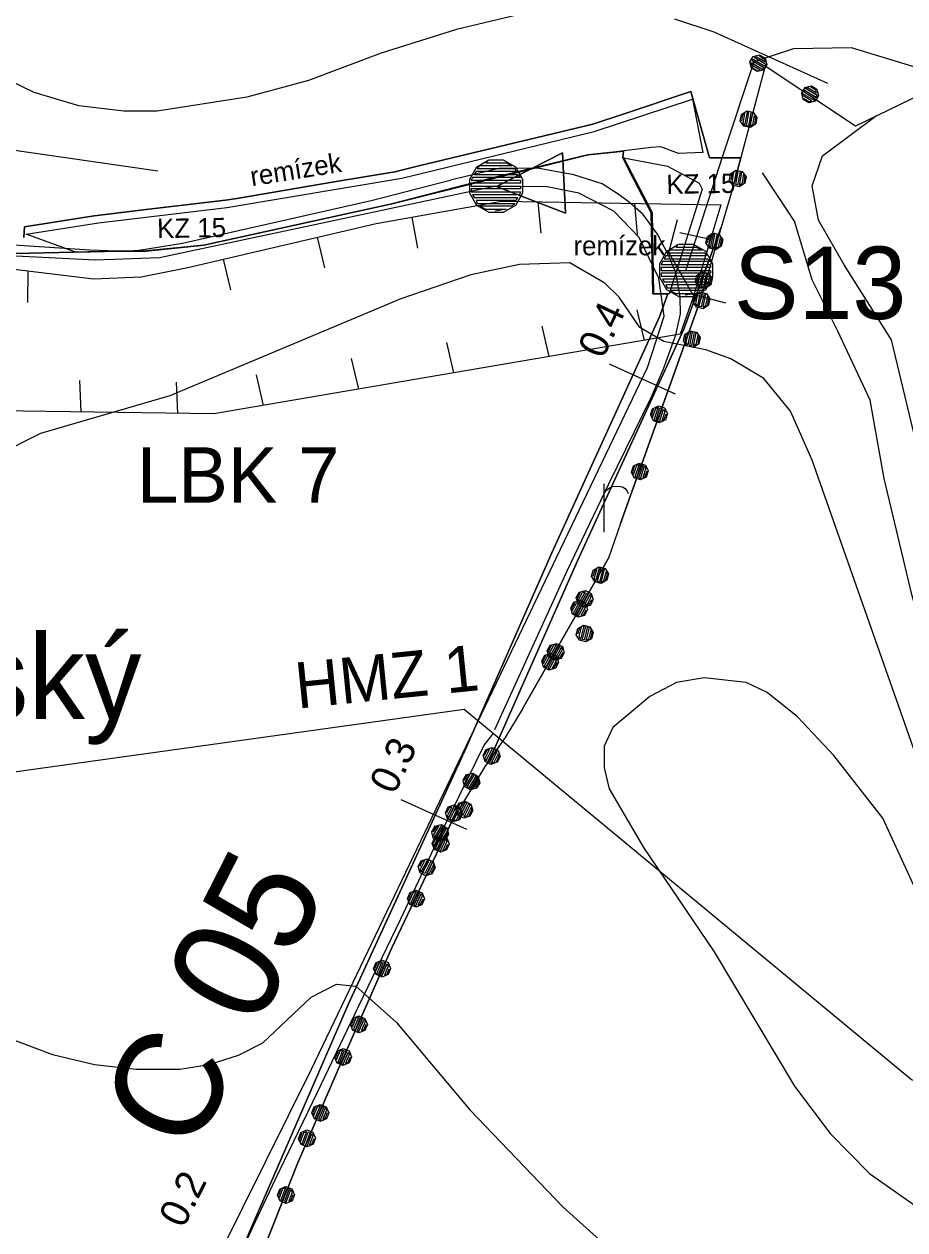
# Model space of a CAD drawing. Extents: x -645676 to -642474, y -1077513 to -1072613.
# Drawn here: x -643934.1 to -643751.8, y -1077150 to -1076900.3 of the extents above; entities that cross this region are included whole.
import ezdxf

# ---------------------------------------------------------------- set-up
doc = ezdxf.new("R2010")
doc.units = 0
for name, color, linetype in [('katastr_ln___zem____popis', 7, 'Continuous'), ('KRAJ_ZELEN_STAV', 7, 'Continuous'), ('Krajinn__zele____popis___stav', 7, 'Continuous'), ('KULTURY_STAV', 7, 'Continuous'), ('KULTURY_ZNACKY', 7, 'Continuous'), ('Lok_ln__biokoridor___navr_en_', 7, 'Continuous'), ('OBVOD_PU', 7, 'Continuous'), ('Odvodnen__cesty_pod_lnou_dren_____navr_en_', 7, 'Continuous'), ('Odvodnen__cesty_pr_kopem___navr_en_', 7, 'Continuous'), ('PC_NAVRH', 7, 'Continuous'), ('PC_OBJ_POPIS_NAVRH', 7, 'Continuous'), ('PC_OBJEKTY_NAVRH', 7, 'Continuous'), ('PC_POPIS_NAVRH', 7, 'Continuous'), ('PC_STAN_NAVRH', 7, 'Continuous'), ('SPRAV_HR_STAV', 7, 'Continuous'), ('USES_BK_NAVRH', 7, 'Continuous'), ('VHO_V_MZ_STAV', 7, 'Continuous'), ('VRSTEVNICE', 7, 'Continuous')]:
    doc.layers.add(name, color=color, linetype=linetype)

# ---------------------------------------------------------------- blocks, each defined once
blk = doc.blocks.new('$406')
blk.add_lwpolyline([(-0.19, 0.72), (0.2, 0.72), (0.54, 0.53), (0.73, 0.19), (0.73, -0.2), (0.54, -0.54), (0.2, -0.73), (-0.19, -0.73), (-0.53, -0.54), (-0.72, -0.2), (-0.72, 0.19), (-0.53, 0.53), (-0.2, 0.72), (-0.28, 0.64), (0.28, 0.64), (0.44, 0.56), (-0.44, 0.56), (-0.52, 0.48), (0.52, 0.48), (0.56, 0.4), (-0.55, 0.4), (-0.6, 0.32), (0.6, 0.32), (0.68, 0.24), (-0.59, 0.24), (-0.65, 0.24), (-0.68, 0.16), (0.59, 0.16), (0.68, 0.16), (0.68, 0.08), (-0.59, 0.08), (-0.68, 0.08), (-0.68, 0), (0.59, 0), (0.68, 0), (0.68, -0.08), (-0.59, -0.08), (-0.68, -0.08), (-0.68, -0.16), (0.59, -0.16), (0.68, -0.16), (0.65, -0.24), (-0.62, -0.24), (-0.65, -0.24), (-0.6, -0.32), (0.6, -0.32), (0.56, -0.4), (-0.55, -0.4), (-0.52, -0.48), (0.52, -0.48), (0.44, -0.56), (-0.44, -0.56), (-0.28, -0.64), (0.28, -0.64), (-0.02, -0.69)])
blk = doc.blocks.new('$944')
blk.add_line((0, 1.5), (0, -1.5))
blk = doc.blocks.new('$920')
for points in [[(0, 0), (-2.8, 1.25), (-2.8, -1.25), (0, 0)], [(-2.8, 1.25), (0, 0), (-2.8, -1.25), (-2.8, 1.25)]]:
    blk.add_lwpolyline(points)
blk = doc.blocks.new('$479')
for points in [[(0, 0), (0, 1.27), (0, 2)], [(0, 1.6), (0.1, 1.73), (0.23, 1.84), (0.37, 1.89), (0.6, 1.9), (0.77, 1.87), (0.87, 1.8), (0.96, 1.7), (1, 1.6)]]:
    blk.add_lwpolyline(points)
blk = doc.blocks.new('$935')
blk.add_lwpolyline([(-2, -1), (-1, 0), (1, 0), (2, -1)])
blk = doc.blocks.new('2$1030')
blk.add_line((0, 0), (0, -0.5))
blk = doc.blocks.new('2$0620')
for points in [[(-1.07, 0.32), (-0.88, 0.13), (-0.88, -0.14), (-1.07, -0.33), (-1.34, -0.33), (-1.53, -0.14), (-1.53, 0.13), (-1.34, 0.32), (-1.07, 0.32), (-1.08, 0.28), (-1.32, 0.28), (-1.4, 0.2), (-1, 0.2), (-0.92, 0.12), (-1.48, 0.12), (-1.48, 0.04), (-0.92, 0.04), (-0.92, -0.04), (-1.48, -0.04), (-1.48, -0.12), (-0.92, -0.12), (-1, -0.2), (-1.4, -0.2), (-1.32, -0.28), (-1.08, -0.28)], [(1.43, 0.32), (1.62, 0.13), (1.62, -0.14), (1.43, -0.33), (1.16, -0.33), (0.97, -0.14), (0.97, 0.13), (1.16, 0.32), (1.43, 0.32), (1.4, 0.28), (1.16, 0.28), (1.08, 0.2), (1.48, 0.2), (1.56, 0.12), (1, 0.12), (1, 0.04), (1.56, 0.04), (1.56, -0.04), (1, -0.04), (1, -0.12), (1.56, -0.12), (1.48, -0.2), (1.08, -0.2), (1.16, -0.28), (1.4, -0.28)]]:
    blk.add_lwpolyline(points)

msp = doc.modelspace()

# ---------------------------------------------------------------- linework, layer by layer
at = {"layer": 'KRAJ_ZELEN_STAV'}
for points in [[(-643933.73, -1076943.82), (-643918.71, -1076941.49), (-643892.15, -1076938.33), (-643855.93, -1076932.25), (-643816.08, -1076922.57), (-643795.76, -1076915.83), (-643793.59, -1076926.92), (-643798.67, -1076927.14), (-643802.3, -1076925.73), (-643804.28, -1076925.84), (-643811.55, -1076926.78), (-643817.4, -1076927.42), (-643836.34, -1076931.93), (-643858.01, -1076937.55), (-643896.9, -1076946.09), (-643908.89, -1076947.24), (-643923.27, -1076947.63), (-643933.73, -1076943.82)], [(-643809.96, -1076927.98), (-643800.94, -1076929.75), (-643794.37, -1076933.23), (-643793.78, -1076934.53), (-643800.6, -1076956.2), (-643803.74, -1076956.17), (-643804.04, -1076939.42), (-643809.96, -1076927.98)]]:
    msp.add_lwpolyline(points, dxfattribs=at)
at = {"layer": 'KULTURY_STAV'}
for points in [[(-643727.59, -1076904.72), (-643762, -1076921.45), (-643780.74, -1076909.01), (-643787.46, -1076934.44), (-643785.76, -1076928), (-643792.24, -1076928.03), (-643796.07, -1076914.3), (-643809.91, -1076918.89), (-643816.39, -1076921.03), (-643829.65, -1076924.22), (-643852.11, -1076929.63), (-643857.38, -1076930.9), (-643869.96, -1076933.01), (-643890.12, -1076936.4), (-643892.46, -1076936.79), (-643908.28, -1076938.67), (-643919.02, -1076939.95), (-643919.66, -1076940.05), (-643934.04, -1076942.28), (-643934.22, -1076944.52)], [(-643934.22, -1076944.52), (-643934.04, -1076942.28), (-643919.66, -1076940.05), (-643919.02, -1076939.95), (-643908.28, -1076938.67), (-643892.46, -1076936.79), (-643890.12, -1076936.4), (-643869.96, -1076933.01), (-643857.38, -1076930.9), (-643852.11, -1076929.63), (-643829.65, -1076924.22), (-643816.39, -1076921.03), (-643809.91, -1076918.89), (-643796.07, -1076914.3), (-643792.24, -1076928.03), (-643785.76, -1076928), (-643787.46, -1076934.44), (-643789.85, -1076942.4), (-643794.58, -1076955.38), (-643797.53, -1076963.48), (-643819.57, -1077011.44), (-643832.54, -1077040.78), (-643837.81, -1077052.71), (-643838.85, -1077054.17), (-643845.44, -1077065.15), (-643858.06, -1077091.75), (-643869.56, -1077117.91), (-643877.5, -1077136.27), (-643884.3, -1077153.42)], [(-644040.86, -1076952.86), (-644022.33, -1076954.94), (-644021.2, -1076954.79), (-644009.66, -1076953.2), (-644000.49, -1076951.94), (-644000.3, -1076951.92), (-643963.54, -1076948.42), (-643935.83, -1076947.82), (-643917.96, -1076947.44), (-643908.9, -1076947.37), (-643896.9, -1076946.09), (-643858.01, -1076937.55), (-643817.4, -1076927.42), (-643811.94, -1076926.83), (-643810.02, -1076926.62)], [(-643894.71, -1077167.13), (-643866.97, -1077103.2), (-643842.95, -1077050.95), (-643839.08, -1077042.14), (-643824.88, -1077009.83), (-643802.58, -1076960.95), (-643800.84, -1076956.21), (-643803.98, -1076956.17), (-643804.28, -1076939.42), (-643808.77, -1076930.75), (-643810.2, -1076927.98), (-643810.02, -1076926.62), (-643811.94, -1076926.83), (-643817.4, -1076927.42), (-643858.01, -1076937.55), (-643896.9, -1076946.09), (-643908.9, -1076947.37), (-643917.96, -1076947.44), (-643935.83, -1076947.82)], [(-643810.02, -1076926.62), (-643810.2, -1076927.98), (-643808.77, -1076930.75), (-643804.28, -1076939.42), (-643803.98, -1076956.17), (-643800.84, -1076956.21), (-643802.58, -1076960.95), (-643824.88, -1077009.83), (-643839.08, -1077042.14), (-643842.95, -1077050.95), (-643866.97, -1077103.2), (-643894.71, -1077167.13)], [(-643789.85, -1076942.4), (-643794.09, -1076957.42), (-643810.67, -1077003.73), (-643813.16, -1077010.92), (-643829.87, -1077040.22), (-643831.03, -1077042.25), (-643834.51, -1077048.04), (-643837.81, -1077052.71), (-643832.54, -1077040.78), (-643819.57, -1077011.44), (-643797.53, -1076963.48), (-643794.58, -1076955.38), (-643789.85, -1076942.4)]]:
    msp.add_lwpolyline(points, dxfattribs=at)
at = {"layer": 'OBVOD_PU'}
msp.add_lwpolyline([(-643727.59, -1076904.72), (-643762, -1076921.45), (-643780.74, -1076909.01), (-643787.46, -1076934.44), (-643789.85, -1076942.4), (-643794.09, -1076957.42), (-643810.67, -1077003.73), (-643813.16, -1077010.92), (-643829.87, -1077040.22), (-643831.03, -1077042.25), (-643834.51, -1077048.04), (-643838.85, -1077054.17), (-643845.44, -1077065.15), (-643858.06, -1077091.75), (-643869.56, -1077117.91), (-643877.5, -1077136.27), (-643884.3, -1077153.42)], dxfattribs=at)
at = {"layer": 'Odvodnen__cesty_pod_lnou_dren_____navr_en_'}
msp.add_lwpolyline([(-644033.07, -1076950.26), (-644020.09, -1076949.84), (-644000.71, -1076948.18), (-643980.82, -1076946.04), (-643969.37, -1076944.99), (-643963.53, -1076944.62), (-643957.69, -1076944.58), (-643951.86, -1076944.87), (-643940.5, -1076945.75), (-643920.52, -1076947.05), (-643914.9, -1076947.25), (-643912.65, -1076947.25), (-643910.4, -1076947.11), (-643908.17, -1076946.81), (-643901.33, -1076945.68), (-643881.81, -1076941.26), (-643862.3, -1076936.85), (-643845.62, -1076932.6)], dxfattribs=at)
at = {"layer": 'Odvodnen__cesty_pr_kopem___navr_en_'}
for points in [[(-643836.71, -1077046.37), (-643821.68, -1077013.51), (-643813.1, -1076995.54), (-643804.23, -1076977.5), (-643801.77, -1076971.68), (-643799.2, -1076964.66), (-643798.21, -1076960.3), (-643798.28, -1076956.84), (-643799.21, -1076951.74), (-643800.82, -1076948.06), (-643803.01, -1076943.85), (-643805.98, -1076939.75), (-643808.82, -1076937.25), (-643810.91, -1076935.65), (-643814.47, -1076933.39), (-643820.29, -1076931.55), (-643827.48, -1076930.19), (-643835.56, -1076930.13), (-643843.22, -1076931.99), (-643845.62, -1076932.6)], [(-643836.98, -1077047.1), (-643838.88, -1077049.61), (-643847.69, -1077067.59), (-643856.21, -1077085.66), (-643864.87, -1077103.69), (-643873.54, -1077121.71), (-643882.2, -1077139.74), (-643886.89, -1077149.68), (-643890.5, -1077157.7), (-643894.07, -1077168.03), (-643896.45, -1077176.29), (-643898.47, -1077186.35), (-643899.68, -1077195.54), (-643900.84, -1077215.28), (-643901.46, -1077235.22), (-643901.81, -1077255.3), (-643902.22, -1077266.76), (-643901.78, -1077275.03), (-643900.81, -1077295.01), (-643899.85, -1077314.98), (-643898.89, -1077334.96), (-643898.86, -1077337.87), (-643898.62, -1077345.72)]]:
    msp.add_lwpolyline(points, dxfattribs=at)
at = {"layer": 'PC_NAVRH'}
for points in [[(-643836.45, -1076933.85), (-643871.36, -1076941.32), (-643906.08, -1076948.75), (-643919.35, -1076949.23), (-643944.11, -1076947.99), (-643966.12, -1076947.14), (-644007.95, -1076951.31), (-644029.76, -1076953.02), (-644037.92, -1076952.26), (-644047.69, -1076947.61), (-644055.18, -1076938.88), (-644069.6, -1076907.09), (-644087.24, -1076870.08), (-644090.18, -1076860.69), (-644095.49, -1076786.67), (-644107.26, -1076627.36), (-644109.1, -1076611.08), (-644113.92, -1076583.41), (-644124.28, -1076545.99), (-644139.39, -1076495.57), (-644142.46, -1076477.03)], [(-643797.12, -1076951.31), (-643789.53, -1076927.82), (-643783.02, -1076908.06), (-643774.79, -1076905.34), (-643762.9, -1076905.19), (-643748.59, -1076909.49), (-643740.43, -1076907.63), (-643712.08, -1076895.74), (-643647.09, -1076856.49), (-643620.93, -1076839.88), (-643580.45, -1076819.48), (-643516.12, -1076783.47), (-643467.4, -1076763.65), (-643449.91, -1076757.58), (-643363.17, -1076715.2), (-643334.98, -1076698.56), (-643297.97, -1076666.45), (-643292.62, -1076653.44), (-643262.84, -1076624.65), (-643243.46, -1076610.62)], [(-643898.91, -1077352.03), (-643901.72, -1077341.53), (-643904.41, -1077287.1), (-643905.27, -1077261.99), (-643903.44, -1077198.67), (-643900.7, -1077177.64), (-643893.62, -1077155.01), (-643874.6, -1077116.77), (-643837.9, -1077040.04), (-643805.1, -1076971.45), (-643801.63, -1076960.8), (-643802.71, -1076952.91), (-643806.77, -1076944.54), (-643812.03, -1076939.04), (-643819.32, -1076935.33), (-643825.86, -1076933.99), (-643836.35, -1076933.93)]]:
    msp.add_lwpolyline(points, dxfattribs=at)
at = {"layer": 'SPRAV_HR_STAV'}
for p, q in [((-643727.59, -1076904.72), (-643762, -1076921.45)), ((-643780.74, -1076909.01), (-643787.46, -1076934.44)), ((-643762, -1076921.45), (-643780.74, -1076909.01)), ((-643787.46, -1076934.44), (-643789.85, -1076942.4)), ((-643789.85, -1076942.4), (-643794.09, -1076957.42)), ((-643810.67, -1077003.73), (-643794.09, -1076957.42)), ((-643810.67, -1077003.73), (-643813.16, -1077010.92)), ((-643829.87, -1077040.22), (-643813.16, -1077010.92)), ((-643831.03, -1077042.25), (-643829.87, -1077040.22)), ((-643831.03, -1077042.25), (-643834.51, -1077048.04)), ((-643834.51, -1077048.04), (-643838.85, -1077054.17)), ((-643838.85, -1077054.17), (-643845.44, -1077065.15)), ((-643858.06, -1077091.75), (-643845.44, -1077065.15)), ((-643869.56, -1077117.91), (-643858.06, -1077091.75)), ((-643877.5, -1077136.27), (-643869.56, -1077117.91)), ((-643884.3, -1077153.42), (-643877.5, -1077136.27))]:
    msp.add_line(p, q, dxfattribs=at)
at = {"layer": 'USES_BK_NAVRH'}
msp.add_lwpolyline([(-644028.19, -1076955.05), (-644022.33, -1076954.94), (-643960.66, -1076949.31), (-643940.82, -1076950.53), (-643919.79, -1076953.1), (-643909.89, -1076952.65), (-643900.21, -1076950.73), (-643861.23, -1076941.62), (-643835.29, -1076937), (-643789.9, -1076937.73), (-643795.7, -1076957.04), (-643798.33, -1076964.54), (-643894.83, -1076981.06), (-643964.11, -1076980.03), (-644028.34, -1076987.54)], dxfattribs=at)
at = {"layer": 'VHO_V_MZ_STAV'}
msp.add_lwpolyline([(-643611.1, -1077161.84), (-643750.44, -1077118.93), (-643843, -1077042.28), (-643989.72, -1077062.69)], dxfattribs=at)
at = {"layer": 'VRSTEVNICE'}
for points in [[(-643831.83, -1076898.39), (-643844.6, -1076901.41), (-643860.21, -1076906.36), (-643875.27, -1076912), (-643888.02, -1076915.48), (-643906.56, -1076918.38), (-643913.51, -1076918.38), (-643922.78, -1076917.22), (-643932.04, -1076914.47), (-643945.95, -1076907.8), (-643961.01, -1076895.35)], [(-643767.72, -1076912.63), (-643791.28, -1076902.01), (-643799.39, -1076899.26)], [(-643906.42, -1076930.77), (-643977.23, -1076920.55), (-643988.53, -1076920.55), (-643996.06, -1076922.28), (-643999.82, -1076924.17), (-644006.63, -1076929.53), (-644011.41, -1076935.32), (-644013.29, -1076938.79), (-644021.54, -1076963.7), (-644029.07, -1076982.82), (-644032.84, -1077000.2), (-644038.49, -1077021.92), (-644043.85, -1077038.43), (-644053.84, -1077062.76), (-644060.07, -1077074.93), (-644076.87, -1077098.24), (-644080.78, -1077105.92), (-644082.8, -1077114.61), (-644084.11, -1077145.02), (-644082.8, -1077157.48)], [(-643769.67, -1076940.89), (-643771.01, -1076933.8), (-643768.81, -1076927.58), (-643757.68, -1076919.24)], [(-643608.51, -1077082.33), (-643635.02, -1077100.42), (-643642.69, -1077104.91), (-643654.86, -1077110.12), (-643667.02, -1077113.01), (-643675.13, -1077113.01), (-643683.24, -1077111.86), (-643695.41, -1077108.38), (-643702.79, -1077104.47), (-643715.25, -1077095.49), (-643721.91, -1077088.4), (-643727.7, -1077080.72), (-643735.23, -1077065.95), (-643740.16, -1077052.91), (-643750.29, -1077018.74), (-643756.09, -1076994.41), (-643758.98, -1076978.19), (-643765.64, -1076963.93), (-643770.99, -1076953.3), (-643774.62, -1076941.11), (-643781.29, -1076931.12)], [(-643745.23, -1077004.54), (-643754.55, -1076965.73), (-643764.33, -1076950.19), (-643769.67, -1076940.89)], [(-643749.57, -1077051.47), (-643771, -1076990.64), (-643775.49, -1076980.5), (-643781, -1076973.7), (-643787.8, -1076969.64), (-643793.02, -1076967.76), (-643801.71, -1076966.02), (-643806.63, -1076963.13), (-643810.97, -1076956.9), (-643813.87, -1076954), (-643821.18, -1076949.74), (-643831.54, -1076950.09), (-643841.68, -1076952.26), (-643856.16, -1076957.19), (-643903.95, -1076977.32), (-643930.76, -1076985.09), (-643940.15, -1076989.77), (-643944.5, -1076992.96), (-643950.44, -1076998.61), (-643955.36, -1077004.69), (-643961.15, -1077016.13)], [(-643750, -1077078.55), (-643756.38, -1077064.79), (-643766.51, -1077051.76), (-643774.04, -1077043.79), (-643780.27, -1077038.72), (-643784.62, -1077036.69), (-643793.31, -1077035.68), (-643799.1, -1077036.69), (-643804.6, -1077039.59), (-643812.28, -1077045.96), (-643814.02, -1077049.87), (-643814.02, -1077054.36), (-643813, -1077058.71), (-643805.91, -1077070.87), (-643791.28, -1077092.45), (-643774.62, -1077120.26), (-643767.24, -1077130.1), (-643759.13, -1077138.36), (-643749.57, -1077145.02)], [(-643941.31, -1077108.81), (-643928.28, -1077113.74), (-643919.59, -1077115.77), (-643910.9, -1077116.78), (-643901.92, -1077116.78), (-643895.84, -1077115.77), (-643889.76, -1077113.88), (-643884.69, -1077111.28), (-643874.7, -1077101.86), (-643869.48, -1077099.11), (-643865.43, -1077099.55), (-643857.03, -1077107.08), (-643841.82, -1077125.18), (-643822.56, -1077145.31), (-643814.31, -1077152.7)]]:
    msp.add_lwpolyline(points, dxfattribs=at)

# ---------------------------------------------------------------- block references
at = {"layer": 'KULTURY_ZNACKY', "xscale": 5, "yscale": 5}
msp.add_blockref('$479', (-643814.07, -1077005.52), dxfattribs=at)
at = {"layer": 'PC_OBJEKTY_NAVRH', "xscale": 5, "yscale": 5.000000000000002, "rotation": 119.97271900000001}
msp.add_blockref('$935', (-643798.19, -1076951.95), dxfattribs=at)
at = {"layer": 'PC_STAN_NAVRH', "xscale": 7.5, "yscale": 7.5}
for p in [(-643836.45, -1076933.85), (-643797.12, -1076951.31)]:
    msp.add_blockref('$406', p, dxfattribs=at)
at = {"layer": 'PC_STAN_NAVRH', "yscale": 4.999999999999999}
for name, p, xscale, rotation in [('$920', (-643836.35, -1076933.93), 4.999999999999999, -177.201925), ('$944', (-643806.2, -1076973.75), 5.000000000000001, 65.571091), ('$944', (-643849.34, -1077063.97), 4.999999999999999, 65.559437)]:
    msp.add_blockref(name, p, dxfattribs=dict(at, xscale=xscale, rotation=rotation))
at = {"layer": 'SPRAV_HR_STAV'}
for p, xscale, yscale, rotation in [((-643776.58, -1076911.77), 5, 5, 148.978536), ((-643785.21, -1076925.93), 5, 4.999999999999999, -100.34829100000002), ((-643792.49, -1076951.2), 5.000000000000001, 5, -102.29176), ((-643794.6, -1076959.24), 5, 5, -101.32659999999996), ((-643804.77, -1076987.25), 5, 5, 71.528504), ((-643816.4, -1077020.27), 5, 5, -104.72271499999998), ((-643821.2, -1077025.02), 5, 5, 61.356072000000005), ((-643822.35, -1077027.06), 5, 5, 61.306766), ((-643840.05, -1077057.25), 5, 5, -116.836184), ((-643844.62, -1077062.32), 5.000000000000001, 5, -121.20193499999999), ((-643847.86, -1077069.17), 5, 4.999999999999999, -116.79960200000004), ((-643850.56, -1077075.94), 5, 4.999999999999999, 65.746459), ((-643862.52, -1077101.89), 5, 5, 67.426212), ((-643870.55, -1077120.21), 4.999999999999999, 5, 67.775982), ((-643877.85, -1077137.15), 5, 5, 69.56491)]:
    msp.add_blockref('2$0620', p, dxfattribs=dict(at, xscale=xscale, yscale=yscale, rotation=rotation))
at = {"layer": 'USES_BK_NAVRH'}
for p, xscale, yscale, rotation in [((-643827.79, -1076937.12), 12.999999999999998, 13.000000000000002, 5.348223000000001), ((-643807.79, -1076937.45), 12.999999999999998, 13.000000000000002, 5.348223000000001), ((-643853.84, -1076940.31), 12.999999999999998, 13.000000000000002, 10.264061), ((-643792.05, -1076944.91), 13, 13, -102.30618700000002), ((-643873.43, -1076944.47), 13, 13, 13.378221), ((-643892.91, -1076949.02), 13, 13, 13.378221), ((-643933.37, -1076951.44), 13.000000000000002, 12.999999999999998, -0.8049130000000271), ((-643805.72, -1076965.81), 13, 13.000000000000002, -166.972813), ((-643825.43, -1076969.18), 13, 13.000000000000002, -166.972813), ((-643845.15, -1076972.56), 13, 13.000000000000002, -166.972813), ((-643864.86, -1076975.93), 13, 13.000000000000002, -166.972813), ((-643922.33, -1076980.65), 13, 12.999999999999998, -177.72420000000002), ((-643884.57, -1076979.31), 13, 13.000000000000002, -166.972813), ((-643902.33, -1076980.95), 13, 12.999999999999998, -177.72420000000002)]:
    msp.add_blockref('2$1030', p, dxfattribs=dict(at, xscale=xscale, yscale=yscale, rotation=rotation))

# ---------------------------------------------------------------- texts
at = {"layer": 'katastr_ln___zem____popis'}
msp.add_text('Bítovanský', height=17.5, dxfattribs=at).set_placement((-644024.28, -1077044.26))
at = {"layer": 'Krajinn__zele____popis___stav'}
for s, rotation, p in [('remízek', 9.11, (-643886.98, -1076933.9)), ('KZ 15', 0.917, (-643801.13, -1076935.49)), ('KZ 15', 0.917, (-643906.57, -1076944.65))]:
    msp.add_text(s, height=4, rotation=rotation, dxfattribs=at).set_placement(p)
msp.add_text('remízek', height=4, dxfattribs=at).set_placement((-643820.4, -1076948.2))
at = {"layer": 'Lok_ln__biokoridor___navr_en_'}
msp.add_text('LBK 7', height=11.5, dxfattribs=at).set_placement((-643910.76, -1076999.45))
at = {"layer": 'PC_OBJ_POPIS_NAVRH'}
msp.add_text('S13', height=15, dxfattribs=at).set_placement((-643787.19, -1076961.39))
at = {"layer": 'PC_POPIS_NAVRH'}
msp.add_text('C 05', height=22, rotation=63.025, dxfattribs=at).set_placement((-643899.38, -1077134.9))
at = {"layer": 'PC_STAN_NAVRH'}
for s, rotation, p in [('0.4', 64.458, (-643814.32, -1076969.87)), ('0.3', 64.458, (-643857.46, -1077060.09)), ('0.2', 63.541, (-643901.13, -1077149.9))]:
    msp.add_text(s, height=6, rotation=rotation, dxfattribs=at).set_placement(p)
at = {"layer": 'VHO_V_MZ_STAV'}
msp.add_text('HMZ 1', height=9.5, rotation=5.787, dxfattribs=at).set_placement((-643877.52, -1077042.07))

doc.saveas('drawing.dxf')
